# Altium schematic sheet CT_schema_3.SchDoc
size 283 x 147 mm
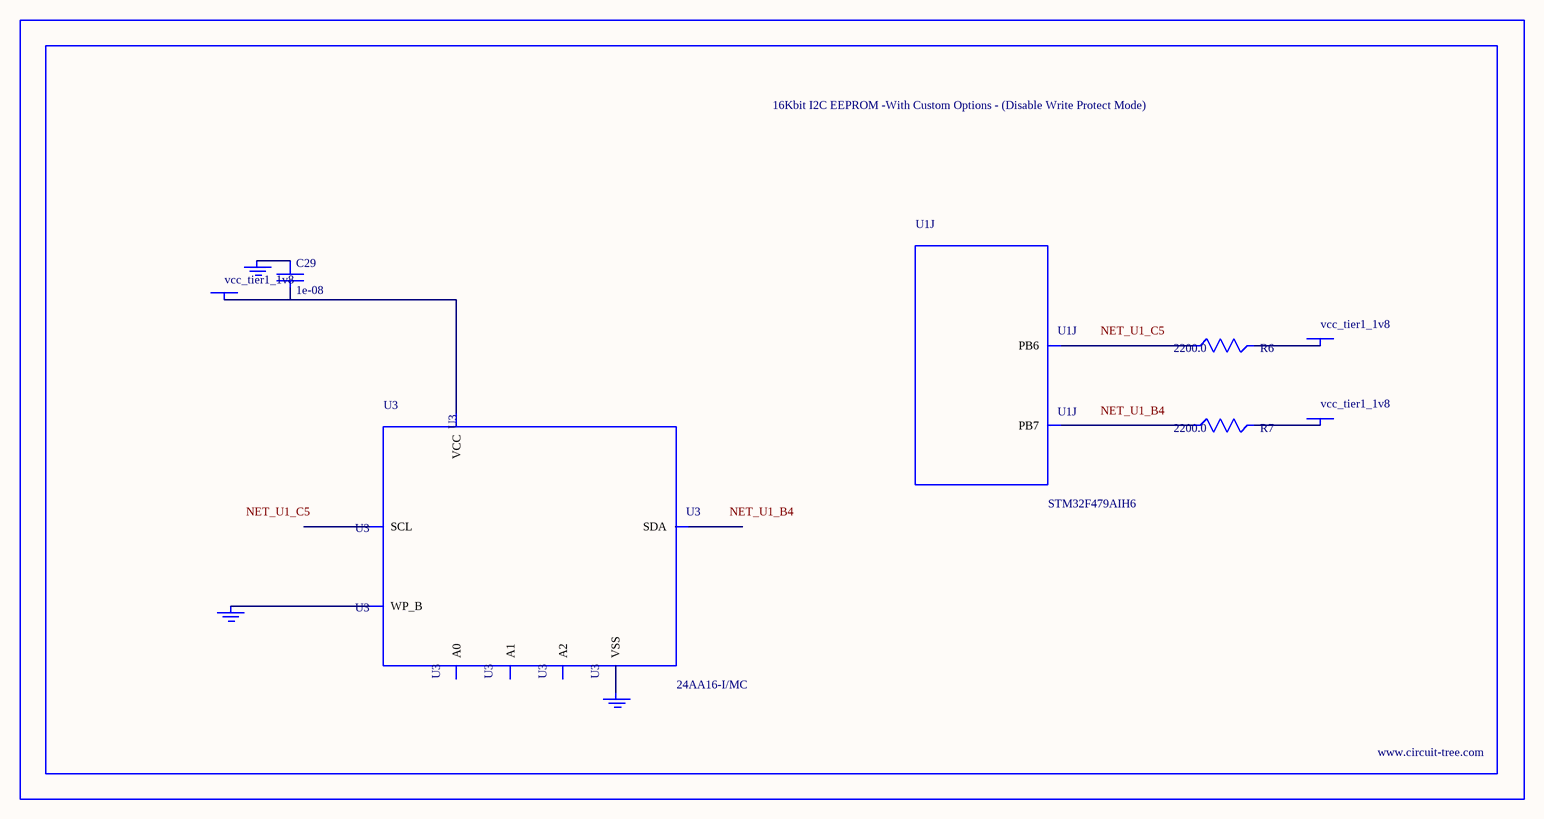
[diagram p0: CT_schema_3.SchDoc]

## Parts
BORDER2  (no value)
C29  1e-08  [C0402]
GND_INSTANCE_2_0  (no value)
GND_INSTANCE_2_1  (no value)
GND_INSTANCE_2_2  (no value)
POWER_INSTANCE_2_0  vcc_tier1_1v8
POWER_INSTANCE_2_1  vcc_tier1_1v8
POWER_INSTANCE_2_2  vcc_tier1_1v8
R6  2200.0  [R0603]
R7  2200.0  [R0603]
U1  STM32F479AIH6  [UFBGA169]  (part J of 14)
U3  24AA16-I/MC  [TDFN-8/6MM]

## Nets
NetC29_1: C29.1 GND_INSTANCE_2_1.0(GND)
NetC29_2: C29.2 POWER_INSTANCE_2_0.0(PWR) U3.8(VCC)
NetGND_INSTANCE_2_0_0: GND_INSTANCE_2_0.0(GND) U3.7(WP_B)
NetGND_INSTANCE_2_2_0: GND_INSTANCE_2_2.0(GND) U3.4(VSS)
NetPOWER_INSTANCE_2_1_0: POWER_INSTANCE_2_1.0(PWR) R6.2
NetPOWER_INSTANCE_2_2_0: POWER_INSTANCE_2_2.0(PWR) R7.2
NetR6_1: R6.1 U1.C5(PB6)
NetR7_1: R7.1 U1.B4(PB7)

Not connected (* = marked no-connect by the designer): U3 1(A0) 2(A1) 3(A2) 5(SDA) 6(SCL)

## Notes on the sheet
- Labels drawn without touching a wire or pin: NET_U1_B4, NET_U1_C5

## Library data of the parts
BORDER2 = BORDER_PAGE2
C29 = C0402C103K3RAC
GND_INSTANCE_2_0-GND_INSTANCE_2_2 = GND
POWER_INSTANCE_2_0-POWER_INSTANCE_2_2 = PWR
R6 R7 = RC0603JR-072K2L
